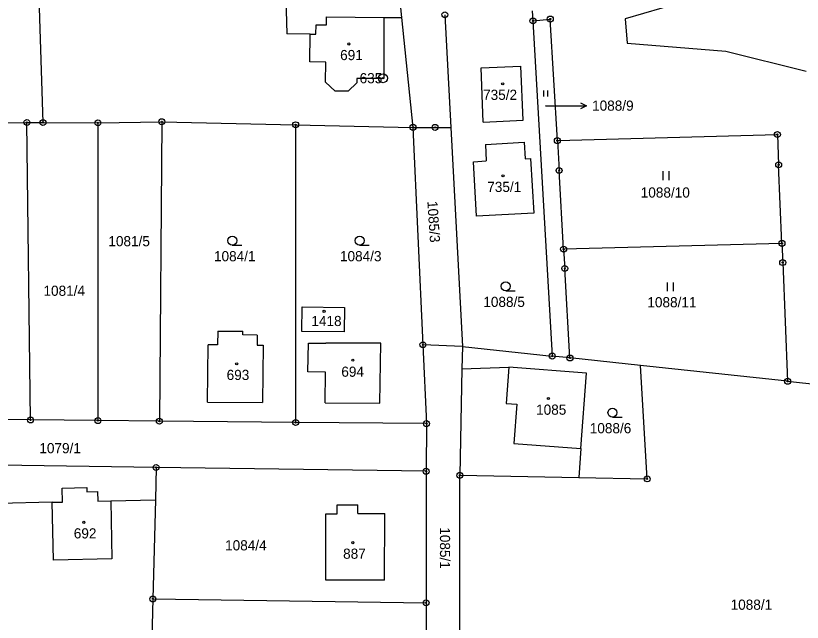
# Model space of a CAD drawing. Extents: x -439246 to -433691, y -1130252 to -1121148.
# Drawn here: x -438464.2 to -438332.6, y -1123676.3 to -1123574.8 of the extents above; entities that cross this region are included whole.
import ezdxf

# ---------------------------------------------------------------- set-up
doc = ezdxf.new("R2010")
doc.units = 0
for name, color, linetype in [('Vrstva 1', 7, 'Continuous'), ('Vrstva 16', 7, 'Continuous'), ('Vrstva 17', 7, 'Continuous'), ('Vrstva 18', 7, 'Continuous'), ('Vrstva 19', 7, 'Continuous'), ('Vrstva 24', 7, 'Continuous'), ('Vrstva 25', 7, 'Continuous'), ('Vrstva 3', 7, 'Continuous'), ('Vrstva 37', 7, 'Continuous'), ('Vrstva 4', 7, 'Continuous')]:
    doc.layers.add(name, color=color, linetype=linetype)

msp = doc.modelspace()

# ---------------------------------------------------------------- linework, layer by layer
at = {"layer": 'Vrstva 1'}
for p, q in [((-438460.93, -1123553.15), (-438459.65, -1123592.69)), ((-438377.77, -1123573.98), (-438377.67, -1123575.68)), ((-438377.67, -1123575.68), (-438374.76, -1123575.38)), ((-438377.67, -1123575.68), (-438374.44, -1123631.75)), ((-438373.58, -1123595.72), (-438374.76, -1123575.38)), ((-438373.58, -1123595.72), (-438336.76, -1123594.69)), ((-438336.76, -1123594.69), (-438336.55, -1123599.76)), ((-438373.58, -1123595.72), (-438373.29, -1123600.71)), ((-438372.53, -1123613.86), (-438373.29, -1123600.71)), ((-438336, -1123612.9), (-438336.55, -1123599.76)), ((-438336, -1123612.9), (-438372.53, -1123613.86)), ((-438372.53, -1123613.86), (-438372.34, -1123617.1)), ((-438336, -1123612.9), (-438335.87, -1123616.11)), ((-438335.87, -1123616.11), (-438335.05, -1123635.97)), ((-438371.48, -1123632.07), (-438372.34, -1123617.1)), ((-438371.48, -1123632.07), (-438374.44, -1123631.75)), ((-438359.69, -1123633.33), (-438371.48, -1123632.07)), ((-438335.05, -1123635.97), (-438359.69, -1123633.33)), ((-438335.05, -1123635.97), (-438300.9, -1123639.64)), ((-438389.9, -1123682.75), (-438389.9, -1123651.69))]:
    msp.add_line(p, q, dxfattribs=at)
for points in [[(-438419.07, -1123570.05), (-438418.87, -1123577.86)], [(-438400.24, -1123569.55), (-438399.66, -1123575.12)], [(-438346.87, -1123570.81), (-438362.22, -1123575.37)], [(-438402.61, -1123575.1), (-438402.59, -1123585.32)], [(-438402.61, -1123575.1), (-438399.66, -1123575.12)], [(-438399.66, -1123575.12), (-438397.74, -1123593.5)], [(-438392.41, -1123574.67), (-438391.41, -1123593.5)], [(-438362.22, -1123575.37), (-438361.88, -1123579.43)], [(-438414.94, -1123577.9), (-438418.87, -1123577.86)], [(-438414.99, -1123582.55), (-438414.94, -1123577.9)], [(-438361.88, -1123579.43), (-438345.39, -1123580.73)], [(-438345.39, -1123580.73), (-438331.95, -1123584.11)], [(-438412.35, -1123582.58), (-438414.99, -1123582.55)], [(-438412.38, -1123585.96), (-438412.35, -1123582.58)], [(-438386.35, -1123583.55), (-438379.69, -1123583.26)], [(-438385.97, -1123592.6), (-438386.35, -1123583.55)], [(-438379.3, -1123592.31), (-438379.69, -1123583.26)], [(-438410.74, -1123587.45), (-438412.38, -1123585.96)], [(-438407.11, -1123586.06), (-438408.57, -1123587.46)], [(-438402.59, -1123585.32), (-438407.11, -1123585.33)], [(-438407.11, -1123585.33), (-438407.11, -1123586.06)], [(-438408.57, -1123587.46), (-438410.74, -1123587.45)], [(-438485.03, -1123592.79), (-438462.35, -1123592.68)], [(-438461.74, -1123642.44), (-438462.35, -1123592.68)], [(-438462.35, -1123592.68), (-438459.65, -1123592.69)], [(-438459.65, -1123592.69), (-438450.47, -1123592.74)], [(-438450.47, -1123592.74), (-438439.77, -1123592.55)], [(-438450.47, -1123592.74), (-438450.47, -1123642.54)], [(-438439.77, -1123592.55), (-438440.18, -1123642.64)], [(-438439.77, -1123592.55), (-438417.38, -1123593.06)], [(-438385.97, -1123592.6), (-438379.3, -1123592.31)], [(-438417.38, -1123593.06), (-438417.38, -1123642.85)], [(-438417.38, -1123593.06), (-438397.74, -1123593.5)], [(-438397.74, -1123593.5), (-438396.08, -1123629.86)], [(-438397.74, -1123593.5), (-438394.03, -1123593.5)], [(-438394.03, -1123593.5), (-438391.41, -1123593.5)], [(-438391.41, -1123593.5), (-438389.47, -1123630.14)], [(-438385.62, -1123596.34), (-438379.11, -1123595.98)], [(-438385.62, -1123596.34), (-438385.47, -1123599.12)], [(-438379.11, -1123595.98), (-438378.96, -1123598.74)], [(-438387.62, -1123599.24), (-438385.47, -1123599.12)], [(-438387.12, -1123608.33), (-438387.62, -1123599.24)], [(-438378.96, -1123598.74), (-438378.06, -1123598.69)], [(-438378.06, -1123598.69), (-438377.49, -1123607.82)], [(-438377.49, -1123607.82), (-438387.12, -1123608.33)], [(-438409.21, -1123623.6), (-438409.28, -1123627.71), (-438416.34, -1123627.62), (-438416.29, -1123623.49), (-438409.21, -1123623.6)], [(-438430.4, -1123627.57), (-438430.43, -1123629.87)], [(-438430.4, -1123627.57), (-438426.2, -1123627.61)], [(-438426.21, -1123628.21), (-438426.2, -1123627.61)], [(-438423.81, -1123628.23), (-438426.21, -1123628.21)], [(-438423.81, -1123628.23), (-438423.83, -1123629.93)], [(-438412.38, -1123634.44), (-438415.33, -1123634.39), (-438415.23, -1123629.58), (-438412.35, -1123629.57)], [(-438403.14, -1123629.57), (-438412.35, -1123629.57)], [(-438403.26, -1123639.63), (-438403.14, -1123629.57)], [(-438432.12, -1123639.45), (-438432.03, -1123629.85)], [(-438430.43, -1123629.87), (-438432.03, -1123629.85)], [(-438423.83, -1123629.93), (-438422.83, -1123629.94)], [(-438422.83, -1123629.94), (-438422.9, -1123639.54)], [(-438389.47, -1123630.14), (-438396.08, -1123629.86)], [(-438396.08, -1123629.86), (-438395.48, -1123643.05)], [(-438389.47, -1123630.14), (-438389.55, -1123633.88)], [(-438389.47, -1123630.14), (-438374.44, -1123631.75)], [(-438389.55, -1123633.88), (-438381.68, -1123633.59)], [(-438368.68, -1123634.58), (-438381.68, -1123633.59)], [(-438358.55, -1123652.29), (-438359.69, -1123633.33)], [(-438412.42, -1123639.57), (-438412.38, -1123634.44)], [(-438389.55, -1123633.88), (-438389.9, -1123651.69)], [(-438369.63, -1123647.21), (-438368.68, -1123634.58)], [(-438432.12, -1123639.45), (-438422.9, -1123639.54)], [(-438412.42, -1123639.57), (-438403.26, -1123639.63)], [(-438461.74, -1123642.44), (-438483.19, -1123642.24)], [(-438450.47, -1123642.54), (-438461.74, -1123642.44)], [(-438440.18, -1123642.64), (-438450.47, -1123642.54)], [(-438417.38, -1123642.85), (-438440.18, -1123642.64)], [(-438395.48, -1123643.05), (-438417.38, -1123642.85)], [(-438395.48, -1123643.05), (-438395.54, -1123651.02)], [(-438369.63, -1123647.21), (-438370, -1123652.07)], [(-438440.72, -1123650.38), (-438466.98, -1123650.01)], [(-438440.72, -1123650.38), (-438440.85, -1123655.78)], [(-438395.54, -1123651.02), (-438440.72, -1123650.38)], [(-438395.54, -1123651.02), (-438395.54, -1123673.02)], [(-438389.9, -1123651.69), (-438370, -1123652.07)], [(-438370, -1123652.07), (-438358.55, -1123652.29)], [(-438448.29, -1123655.96), (-438440.85, -1123655.78)], [(-438448.29, -1123655.96), (-438448.11, -1123665.66)], [(-438440.85, -1123655.78), (-438441.27, -1123672.37)], [(-438458.09, -1123656.2), (-438467.04, -1123656.42)], [(-438457.91, -1123665.9), (-438458.09, -1123656.2)], [(-438410.4, -1123658.13), (-438410.4, -1123656.64)], [(-438410.4, -1123656.64), (-438406.96, -1123656.64)], [(-438406.96, -1123658.09), (-438406.96, -1123656.64)], [(-438412.32, -1123669.21), (-438412.3, -1123658.13)], [(-438412.3, -1123658.13), (-438410.4, -1123658.13)], [(-438406.96, -1123658.09), (-438402.47, -1123658.1)], [(-438402.49, -1123669.22), (-438402.47, -1123658.1)], [(-438448.11, -1123665.66), (-438457.91, -1123665.9)], [(-438402.49, -1123669.22), (-438412.32, -1123669.21)], [(-438441.27, -1123672.37), (-438441.82, -1123694.37)], [(-438441.27, -1123672.37), (-438395.54, -1123673.02)], [(-438395.54, -1123673.02), (-438395.54, -1123695.02)]]:
    msp.add_lwpolyline(points, dxfattribs=at)
at = {"layer": 'Vrstva 16'}
msp.add_line((-438371.71, -1123589.88), (-438368.71, -1123589.87), dxfattribs=at)
for points in [[(-438375.58, -1123589.89), (-438371.71, -1123589.88)], [(-438369.71, -1123589.37), (-438368.71, -1123589.87), (-438369.71, -1123590.37)]]:
    msp.add_lwpolyline(points, dxfattribs=at)
at = {"layer": 'Vrstva 24'}
for centre, radius in [((-438392.41, -1123574.67), 0.5), ((-438377.67, -1123575.68), 0.5), ((-438377.67, -1123575.68), 0.1), ((-438374.76, -1123575.38), 0.5), ((-438374.76, -1123575.38), 0.1), ((-438402.75, -1123585.27), 0.75), ((-438402.75, -1123585.27), 0.1), ((-438462.35, -1123592.68), 0.5), ((-438462.35, -1123592.68), 0.1), ((-438459.65, -1123592.69), 0.5), ((-438459.65, -1123592.69), 0.1), ((-438450.47, -1123592.74), 0.5), ((-438450.47, -1123592.74), 0.1), ((-438439.77, -1123592.55), 0.5), ((-438439.77, -1123592.55), 0.1), ((-438417.38, -1123593.06), 0.5), ((-438417.38, -1123593.06), 0.1), ((-438397.74, -1123593.5), 0.5), ((-438397.74, -1123593.5), 0.1), ((-438394.03, -1123593.5), 0.5), ((-438394.03, -1123593.5), 0.1), ((-438336.76, -1123594.69), 0.5), ((-438373.58, -1123595.72), 0.5), ((-438336.76, -1123594.69), 0.1), ((-438373.58, -1123595.72), 0.1), ((-438336.55, -1123599.76), 0.5), ((-438373.29, -1123600.71), 0.5), ((-438373.29, -1123600.71), 0.1), ((-438336.55, -1123599.76), 0.1), ((-438336, -1123612.9), 0.5), ((-438372.53, -1123613.86), 0.5), ((-438372.53, -1123613.86), 0.1), ((-438336, -1123612.9), 0.1), ((-438372.34, -1123617.1), 0.5), ((-438335.87, -1123616.11), 0.5), ((-438335.87, -1123616.11), 0.1), ((-438372.34, -1123617.1), 0.1), ((-438396.08, -1123629.86), 0.5), ((-438396.08, -1123629.86), 0.1), ((-438374.44, -1123631.75), 0.5), ((-438374.44, -1123631.75), 0.1), ((-438371.48, -1123632.07), 0.5), ((-438371.48, -1123632.07), 0.1), ((-438335.05, -1123635.97), 0.5), ((-438335.05, -1123635.97), 0.1), ((-438461.74, -1123642.44), 0.5), ((-438461.74, -1123642.44), 0.1), ((-438450.47, -1123642.54), 0.5), ((-438450.47, -1123642.54), 0.1), ((-438440.18, -1123642.64), 0.5), ((-438440.18, -1123642.64), 0.1), ((-438417.38, -1123642.85), 0.5), ((-438417.38, -1123642.85), 0.1), ((-438395.48, -1123643.05), 0.5), ((-438395.48, -1123643.05), 0.1), ((-438440.72, -1123650.38), 0.5), ((-438440.72, -1123650.38), 0.1), ((-438395.54, -1123651.02), 0.5), ((-438395.54, -1123651.02), 0.1), ((-438389.9, -1123651.69), 0.5), ((-438389.9, -1123651.69), 0.1), ((-438358.55, -1123652.29), 0.5), ((-438358.55, -1123652.29), 0.1), ((-438441.27, -1123672.37), 0.5), ((-438441.27, -1123672.37), 0.1), ((-438395.54, -1123673.02), 0.5), ((-438395.54, -1123673.02), 0.1)]:
    msp.add_circle(centre, radius, dxfattribs=at)
at = {"layer": 'Vrstva 25'}
for p, q in [((-438375.86, -1123588.33), (-438375.86, -1123587.32)), ((-438375.2, -1123588.33), (-438375.2, -1123587.32)), ((-438355.85, -1123602.31), (-438355.85, -1123600.81)), ((-438354.85, -1123602.31), (-438354.85, -1123600.81)), ((-438427.97, -1123613.19), (-438426.37, -1123613.19)), ((-438406.67, -1123613.19), (-438405.07, -1123613.19)), ((-438355.16, -1123620.92), (-438355.16, -1123619.42)), ((-438354.16, -1123620.92), (-438354.16, -1123619.42)), ((-438382.22, -1123620.83), (-438380.62, -1123620.83)), ((-438364.36, -1123641.96), (-438362.76, -1123641.96))]:
    msp.add_line(p, q, dxfattribs=at)
for centre, radius in [((-438408.47, -1123579.55), 0.175), ((-438382.73, -1123586.2), 0.175), ((-438382.67, -1123601.6), 0.175), ((-438427.97, -1123612.44), 0.75), ((-438406.67, -1123612.44), 0.75), ((-438382.22, -1123620.08), 0.75), ((-438412.62, -1123624.27), 0.175), ((-438407.81, -1123632.42), 0.175), ((-438427.24, -1123633.05), 0.175), ((-438375.08, -1123638.86), 0.175), ((-438364.36, -1123641.21), 0.75), ((-438452.82, -1123659.55), 0.175), ((-438407.79, -1123662.95), 0.175)]:
    msp.add_circle(centre, radius, dxfattribs=at)
at = {"layer": 'Vrstva 3'}
for points in [[(-438412.22, -1123576.35), (-438412.21, -1123575.03)], [(-438412.21, -1123575.03), (-438402.61, -1123575.1)], [(-438402.61, -1123575.1), (-438402.59, -1123585.32)], [(-438413.98, -1123577.91), (-438413.96, -1123576.33)], [(-438413.96, -1123576.33), (-438412.22, -1123576.35)], [(-438414.99, -1123582.55), (-438414.94, -1123577.9)], [(-438414.94, -1123577.9), (-438413.98, -1123577.91)], [(-438412.35, -1123582.58), (-438414.99, -1123582.55)], [(-438412.38, -1123585.96), (-438412.35, -1123582.58)], [(-438386.35, -1123583.55), (-438379.69, -1123583.26)], [(-438385.97, -1123592.6), (-438386.35, -1123583.55)], [(-438379.3, -1123592.31), (-438379.69, -1123583.26)], [(-438410.74, -1123587.45), (-438412.38, -1123585.96)], [(-438407.11, -1123586.06), (-438408.57, -1123587.46)], [(-438402.59, -1123585.32), (-438407.11, -1123585.33)], [(-438407.11, -1123585.33), (-438407.11, -1123586.06)], [(-438408.57, -1123587.46), (-438410.74, -1123587.45)], [(-438385.97, -1123592.6), (-438379.3, -1123592.31)], [(-438385.62, -1123596.34), (-438379.11, -1123595.98)], [(-438385.62, -1123596.34), (-438385.47, -1123599.12)], [(-438379.11, -1123595.98), (-438378.96, -1123598.74)], [(-438387.62, -1123599.24), (-438385.47, -1123599.12)], [(-438387.12, -1123608.33), (-438387.62, -1123599.24)], [(-438378.96, -1123598.74), (-438378.06, -1123598.69)], [(-438378.06, -1123598.69), (-438377.49, -1123607.82)], [(-438377.49, -1123607.82), (-438387.12, -1123608.33)], [(-438409.21, -1123623.6), (-438409.28, -1123627.71), (-438416.34, -1123627.62), (-438416.29, -1123623.49), (-438409.21, -1123623.6)], [(-438430.4, -1123627.57), (-438430.43, -1123629.87)], [(-438430.4, -1123627.57), (-438426.2, -1123627.61)], [(-438426.21, -1123628.21), (-438426.2, -1123627.61)], [(-438423.81, -1123628.23), (-438426.21, -1123628.21)], [(-438423.81, -1123628.23), (-438423.83, -1123629.93)], [(-438412.38, -1123634.44), (-438415.33, -1123634.39), (-438415.23, -1123629.58), (-438412.35, -1123629.57)], [(-438403.14, -1123629.57), (-438412.35, -1123629.57)], [(-438403.26, -1123639.63), (-438403.14, -1123629.57)], [(-438432.12, -1123639.45), (-438432.03, -1123629.85)], [(-438430.43, -1123629.87), (-438432.03, -1123629.85)], [(-438423.83, -1123629.93), (-438422.83, -1123629.94)], [(-438422.83, -1123629.94), (-438422.9, -1123639.54)], [(-438381.68, -1123633.59), (-438382.13, -1123639.66)], [(-438368.68, -1123634.58), (-438381.68, -1123633.59)], [(-438412.42, -1123639.57), (-438412.38, -1123634.44)], [(-438369.63, -1123647.21), (-438368.68, -1123634.58)], [(-438432.12, -1123639.45), (-438422.9, -1123639.54)], [(-438412.42, -1123639.57), (-438403.26, -1123639.63)], [(-438382.13, -1123639.66), (-438380.39, -1123639.79)], [(-438380.39, -1123639.79), (-438380.88, -1123646.36)], [(-438380.88, -1123646.36), (-438369.63, -1123647.21)], [(-438456.44, -1123653.82), (-438452.34, -1123653.74)], [(-438456.39, -1123656.17), (-438456.44, -1123653.82)], [(-438452.34, -1123653.74), (-438452.32, -1123654.44)], [(-438452.32, -1123654.44), (-438450.52, -1123654.4)], [(-438450.52, -1123654.4), (-438450.49, -1123656)], [(-438450.49, -1123656), (-438448.29, -1123655.96)], [(-438448.29, -1123655.96), (-438448.11, -1123665.66)], [(-438458.09, -1123656.2), (-438456.39, -1123656.17)], [(-438457.91, -1123665.9), (-438458.09, -1123656.2)], [(-438410.4, -1123658.13), (-438410.4, -1123656.64)], [(-438410.4, -1123656.64), (-438406.96, -1123656.64)], [(-438406.96, -1123658.09), (-438406.96, -1123656.64)], [(-438412.32, -1123669.21), (-438412.3, -1123658.13)], [(-438412.3, -1123658.13), (-438410.4, -1123658.13)], [(-438406.96, -1123658.09), (-438402.47, -1123658.1)], [(-438402.49, -1123669.22), (-438402.47, -1123658.1)], [(-438448.11, -1123665.66), (-438457.91, -1123665.9)], [(-438402.49, -1123669.22), (-438412.32, -1123669.21)]]:
    msp.add_lwpolyline(points, dxfattribs=at)
at = {"layer": 'Vrstva 37'}
for centre in [(-438408.47, -1123579.55), (-438382.73, -1123586.2), (-438382.67, -1123601.6), (-438412.62, -1123624.27), (-438407.81, -1123632.42), (-438427.24, -1123633.05), (-438375.08, -1123638.86), (-438452.82, -1123659.55), (-438407.79, -1123662.95)]:
    msp.add_circle(centre, 0.175, dxfattribs=at)
at = {"layer": 'Vrstva 4'}
for points in [[(-438412.22, -1123576.35), (-438412.21, -1123575.03)], [(-438412.21, -1123575.03), (-438402.61, -1123575.1)], [(-438413.98, -1123577.91), (-438413.96, -1123576.33)], [(-438413.96, -1123576.33), (-438412.22, -1123576.35)], [(-438414.94, -1123577.9), (-438413.98, -1123577.91)], [(-438381.68, -1123633.59), (-438382.13, -1123639.66)], [(-438382.13, -1123639.66), (-438380.39, -1123639.79)], [(-438380.39, -1123639.79), (-438380.88, -1123646.36)], [(-438380.88, -1123646.36), (-438369.63, -1123647.21)], [(-438456.44, -1123653.82), (-438452.34, -1123653.74)], [(-438456.39, -1123656.17), (-438456.44, -1123653.82)], [(-438452.34, -1123653.74), (-438452.32, -1123654.44)], [(-438452.32, -1123654.44), (-438450.52, -1123654.4)], [(-438450.52, -1123654.4), (-438450.49, -1123656)], [(-438450.49, -1123656), (-438448.29, -1123655.96)], [(-438458.09, -1123656.2), (-438456.39, -1123656.17)]]:
    msp.add_lwpolyline(points, dxfattribs=at)

# ---------------------------------------------------------------- texts
at = {"layer": 'Vrstva 16'}
msp.add_text('1088/9', height=1.7, dxfattribs=at).set_placement((-438367.77, -1123590.71))
at = {"layer": 'Vrstva 17'}
msp.add_text('635', height=1.7, dxfattribs=at).set_placement((-438406.67, -1123586.12))
at = {"layer": 'Vrstva 18'}
for s, height, p in [('1088/9', 0.1, (-438375.81, -1123589.88)), ('1088/10', 1.7, (-438359.63, -1123605.24)), ('1081/5', 1.7, (-438448.71, -1123613.38)), ('1084/1', 1.7, (-438431.04, -1123615.89)), ('1084/3', 1.7, (-438409.96, -1123615.89)), ('1081/4', 1.7, (-438459.57, -1123621.67)), ('1088/5', 1.7, (-438385.97, -1123623.53)), ('1088/11', 1.7, (-438358.52, -1123623.59)), ('1088/6', 1.7, (-438368.16, -1123644.66)), ('1079/1', 1.7, (-438460.26, -1123648)), ('1084/4', 1.7, (-438429.18, -1123664.25)), ('1088/1', 1.7, (-438344.59, -1123674.18))]:
    msp.add_text(s, height=height, dxfattribs=at).set_placement(p)
for s, rotation, p in [('1085/3', 273.6882, (-438395.34, -1123605.87)), ('1085/1', 270, (-438393.23, -1123660.38))]:
    msp.add_text(s, height=1.7, rotation=rotation, dxfattribs=at).set_placement(p)
at = {"layer": 'Vrstva 19'}
for s, p in [('691', (-438409.93, -1123582.25)), ('735/2', (-438386.01, -1123588.9)), ('735/1', (-438385.31, -1123604.3)), ('1418', (-438414.74, -1123626.73)), ('694', (-438409.73, -1123635.21)), ('693', (-438428.92, -1123635.75)), ('1085', (-438377.14, -1123641.56)), ('692', (-438454.5, -1123662.25)), ('887', (-438409.43, -1123665.65))]:
    msp.add_text(s, height=1.7, dxfattribs=at).set_placement(p)

doc.saveas('drawing.dxf')
